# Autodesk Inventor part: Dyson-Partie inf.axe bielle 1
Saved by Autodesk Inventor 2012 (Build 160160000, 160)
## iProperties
Created: 2012-11
Part Number: Dyson-Partie inf.axe bielle 1
Material: Default
Document SubType Name: Modeling
Designer: Administrateur
Density: 1 g/cm^3
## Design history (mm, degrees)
node "Dyson-Partie inf.axe bielle 11"
node "Dyson-Partie inf.axe bielle 1"
node "Base1"
